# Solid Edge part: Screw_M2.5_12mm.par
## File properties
Author: hhakima
Template: Normal.par
Last saved by: hhakima
Revision: 4
Application: Solid Edge
Material: Stainless steel
Face Style: Steel
Fill Style: ANSI32(Steel)
Virtual Style: Stainless steel
Coef. of Thermal Exp: 1.6e-05
Thermal Conductivity: 17.0
Specific Heat: 502.0
Modulus of Elasticity: 193053196000.0
Poission's Ratio: 0.29
Yield Stress: 310264065.0
Ultimate Stress: 641212401.0
Elongation: 0.0
Density: 7750.000 kg/m^3
Accuracy: 0.990
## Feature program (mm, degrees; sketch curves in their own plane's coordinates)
body "unnamed Body 1"
sketch for "unnamed Cutout 1" plane through (0, 0, -14.5) normal (0, 0, -1) x-axis (1, 0, 0)
  circle centre (-1.6, 0) radius 0.25
extrude "unnamed Cutout 1" cut finite 0.1 along -normal
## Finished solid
Body 1: solid body, 26 faces, 43 edges, 20 vertices.
  Faces by surface: plane 11, cone 9, cylinder 4, spline 2
  Edges by curve: circle 17, line 12, intersection 10, spline 4
Bounding box of the edges (mm; curved faces can reach further): 4.500 x 4.500 x 14.500, from (-2.25, -2.25, -14.5) to (2.25, 2.25, 0).
Cylindrical faces by radius (mm): R0.25 x1, R0.9577 x1, R1.25 x1, R2.25 x1
Conical faces (half-angle, radius in mm at the cone's reference point): 45 deg R1.1547 x6, 45 deg R2.025 x1, 45 deg R2.25 x1, 55 deg R0.7037 x1
Planar faces by outward normal: +x 1, +z 2, -x 1, -z 3, oblique 4
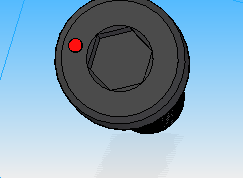
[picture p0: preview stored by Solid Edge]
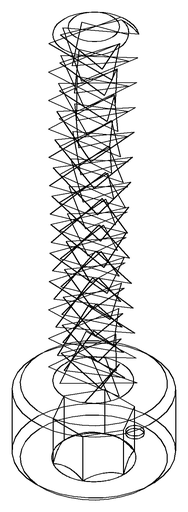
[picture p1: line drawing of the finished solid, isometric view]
